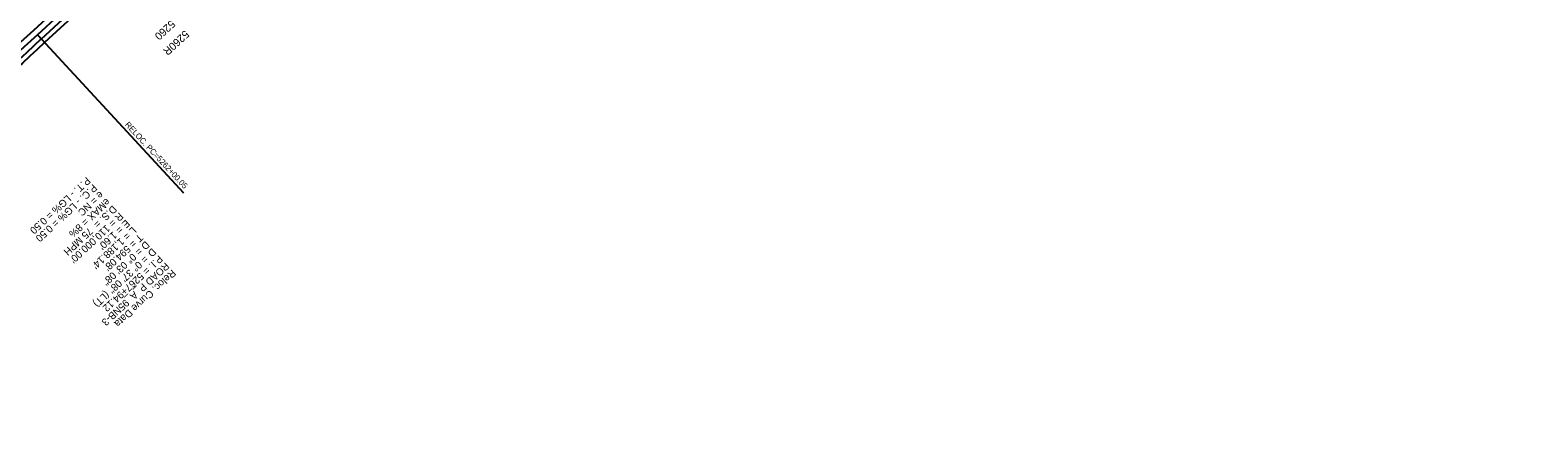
# Model space of a CAD drawing. Extents: x 2160876 to 2175625, y 601634 to 617693.
# Drawn here: x 2165605 to 2168721, y 606769 to 607589 of the extents above; entities that cross this region are included whole.
import ezdxf

# ---------------------------------------------------------------- set-up
doc = ezdxf.new("R2010")
doc.units = 0
for name, color, linetype in [('RD_HC_CL_Rel', 7, 'Continuous'), ('RD_HC_Data_Rel', 7, 'Continuous'), ('RD_HC_Data_Tic_Rel', 7, 'Continuous'), ('RD_HC_TX_Rel_Sta50', 7, 'Continuous'), ('RD_HC_TX_Sta50', 7, 'Continuous'), ('RD_PD_Final_LnLine', 7, 'Continuous'), ('RD_PD_Final_TrvlWay', 7, 'Continuous')]:
    doc.layers.add(name, color=color, linetype=linetype)

msp = doc.modelspace()

# ---------------------------------------------------------------- linework, layer by layer
at = {"layer": 'RD_HC_CL_Rel'}
msp.add_line((2168705.8, 610428.6), (2165620.1, 607579.3), dxfattribs=at)
msp.add_arc((2240245.2, 526764.1), 110000, 132.719474, 133.338341, dxfattribs=at)
at = {"layer": 'RD_HC_Data_Rel'}
msp.add_line((2165620.1, 607579.3), (2165922.1, 607252.3), dxfattribs=at)
at = {"layer": 'RD_HC_Data_Tic_Rel'}
msp.add_line((2165620.2, 607579.4), (2165625.6, 607573.5), dxfattribs=at)
at = {"layer": 'RD_PD_Final_LnLine'}
for p, q in [((2168697.7, 610437.5), (2165612, 607588.1)), ((2168705.8, 610428.6), (2165620.1, 607579.3)), ((2168714, 610419.8), (2165628.3, 607570.5))]:
    msp.add_line(p, q, dxfattribs=at)
for radius, end in [(110012, 133.338341), (110000, 133.338341), (109988, 133.067682)]:
    msp.add_arc((2240245.2, 526764.1), radius, 132.719474, end, dxfattribs=at)
at = {"layer": 'RD_PD_Final_TrvlWay'}
msp.add_line((2168720.7, 610412.5), (2165635.1, 607563.2), dxfattribs=at)
msp.add_arc((2240245.2, 526764.1), 109978, 132.719474, 133.067545, dxfattribs=at)

# ---------------------------------------------------------------- texts
at = {"layer": 'RD_HC_Data_Rel'}
for s, height, rotation, p in [('RELOC. PC=5262+00.05', 12, 312.7195, (2165800.3, 607392.7)), ('P.T. - LG% = 0.50', 15, 222.7195, (2165721.6, 607286.1)), ('P.C. - LG% = 0.50', 15, 222.7195, (2165735.2, 607271.4)), ('e = NC', 15, 222.7195, (2165748.7, 607256.8)), ('D.S. =  75 MPH', 15, 222.7195, (2165775.9, 607227.4)), ('eMAX = 8%', 15, 222.7195, (2165762.3, 607242.1)), ("R = 110,000.00'", 15, 222.7195, (2165789.4, 607212.7)), ("E = 1.60'", 15, 222.7195, (2165803, 607198)), ("L = 1,188.14'", 15, 222.7195, (2165816.6, 607183.3)), ("T = 594.08'", 15, 222.7195, (2165830.1, 607168.6)), ('P.I. = 5267+94.12', 15, 222.7195, (2165870.9, 607124.5)), ('D = 0° 03\' 08"', 15, 222.7195, (2165843.7, 607153.9)), ('D', 15, 222.7195, (2165857.3, 607139.2)), ('    = 0° 37\' 08" (LT)', 15, 222.7195, (2165857.3, 607139.2)), ('ROAD P_A_95NB-3', 15, 222.7195, (2165884.4, 607109.8)), ('Reloc. Curve Data', 15, 222.7195, (2165898, 607095.1))]:
    msp.add_text(s, height=height, rotation=rotation, dxfattribs=at).set_placement(p)
at = {"layer": 'RD_HC_TX_Rel_Sta50'}
msp.add_text('5260R', height=16, rotation=222.7195, dxfattribs=at).set_placement((2165924.8, 607589.6))
at = {"layer": 'RD_HC_TX_Sta50'}
msp.add_text('5260', height=16, rotation=222.7195, dxfattribs=at).set_placement((2165896.1, 607610.9))

doc.saveas('drawing.dxf')
